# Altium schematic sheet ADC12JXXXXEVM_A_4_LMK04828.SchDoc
size 431 x 279 mm; Date: Not shown in title block; ApprovedBy: Not shown in title block; CheckedBy: Not shown in title block; Author: Not shown in title block; CompanyName: Not shown in title block; Engineer: Not shown in title block; Organization: Not shown in title block; Address1: Not shown in title block; Address2: Not shown in title block; Address3: Not shown in title block; Address4: Not shown in title block; DocumentNumber: 4; Revision: Use project parameter SCH_Rev; SheetNumber: 4; SheetTotal: 7; PageSetup: Record=PageOptions|CenterHorizontal=True|CenterVertical=True|PrintScale=0.47|XCorrection=1.00|YCorrection=1.00|PrintKind=0|BorderSize=5000000|LeftOffset=0|BottomOffset=0|Orientation=2|PaperLength=1000|PaperWidth=1000|Scale=100|PaperSource=7|PrintQuality=600|MediaType=1|DitherType=10|PaperKind=11" x 17"|PrintScaleMode=1
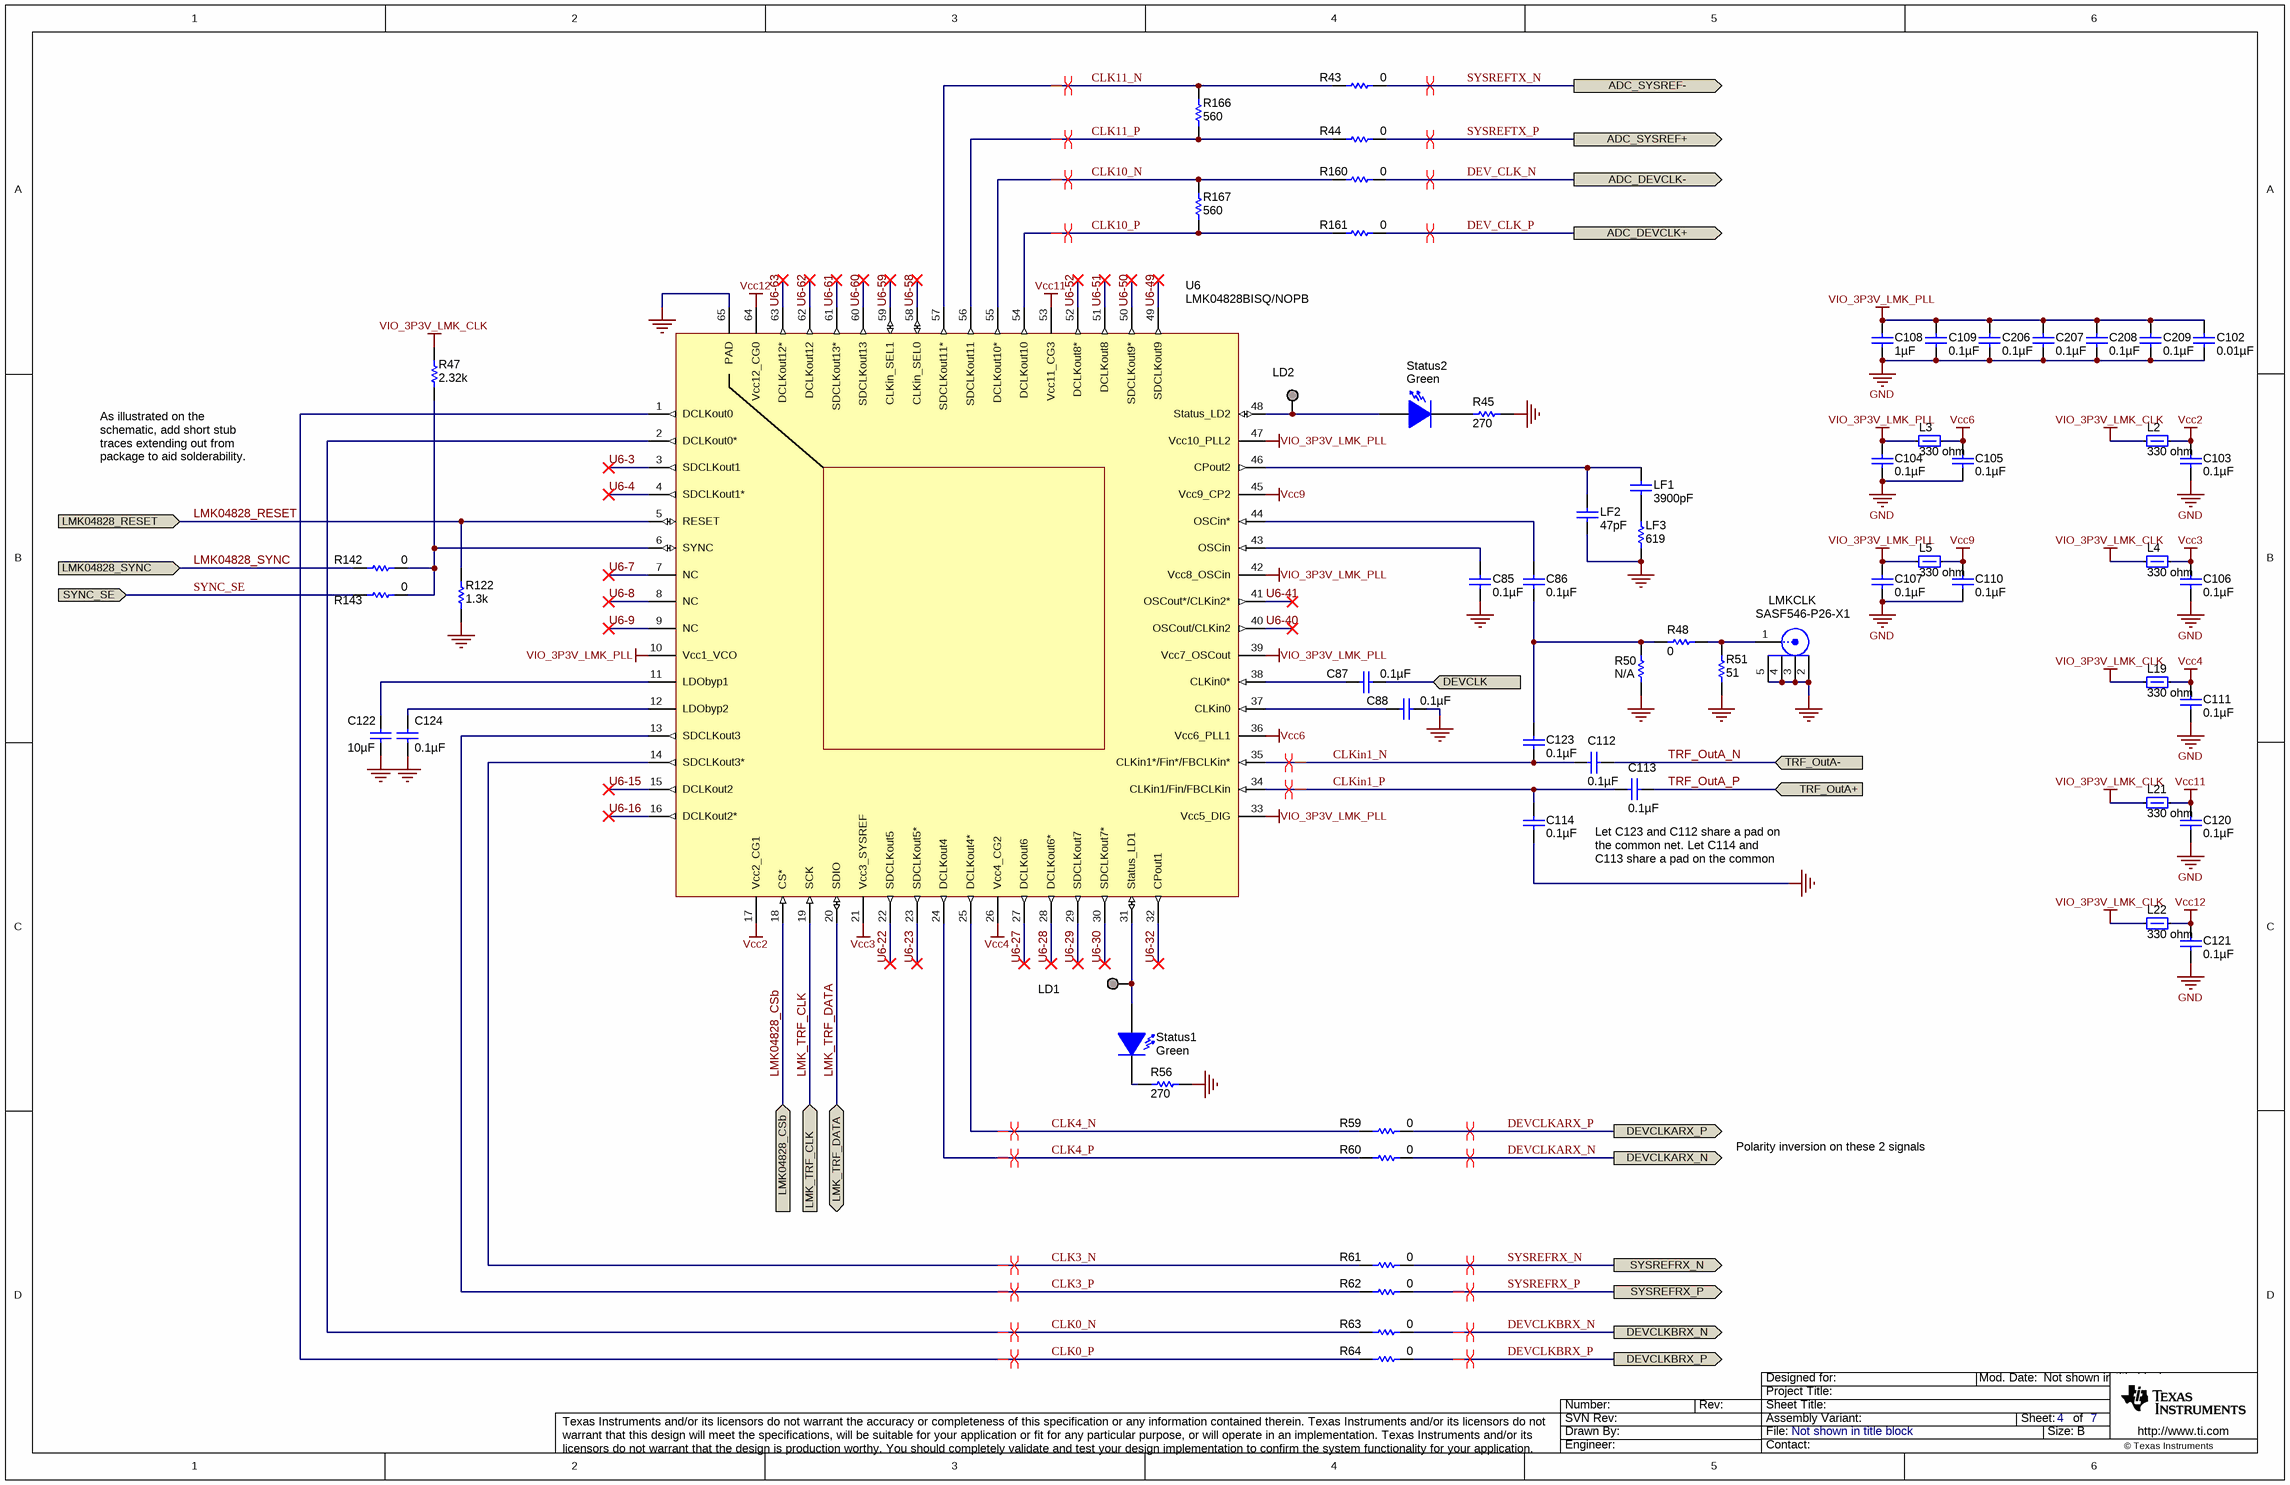
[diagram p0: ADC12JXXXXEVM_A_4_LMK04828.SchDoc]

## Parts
C85  ValueDisplayed: 0.1µF  [0402L]  (hidden comment: C1005X5R1A104K)
C86  ValueDisplayed: 0.1µF  [0402L]  (hidden comment: C1005X5R1A104K)
C87  ValueDisplayed: 0.1µF  [0402L]  (hidden comment: C1005X5R1A104K)
C88  ValueDisplayed: 0.1µF  [0402L]  (hidden comment: C1005X5R1A104K)
C102  ValueDisplayed: 0.01µF  [0402L]  (hidden comment: C1005X7R1C103K)
C103  ValueDisplayed: 0.1µF  [0402L]  (hidden comment: C1005X5R1A104K)
C104  ValueDisplayed: 0.1µF  [0402L]  (hidden comment: C1005X5R1A104K)
C105  ValueDisplayed: 0.1µF  [0402L]  (hidden comment: C1005X5R1A104K)
C106  ValueDisplayed: 0.1µF  [0402L]  (hidden comment: C1005X5R1A104K)
C107  ValueDisplayed: 0.1µF  [0402L]  (hidden comment: C1005X5R1A104K)
C108  ValueDisplayed: 1µF  [0603L]  (hidden comment: C1608X5R1C105K)
C109  ValueDisplayed: 0.1µF  [0402L]  (hidden comment: C1005X5R1A104K)
C110  ValueDisplayed: 0.1µF  [0402L]  (hidden comment: C1005X5R1A104K)
C111  ValueDisplayed: 0.1µF  [0402L]  (hidden comment: C1005X5R1A104K)
C112  ValueDisplayed: 0.1µF  [0402L]  (hidden comment: C1005X5R1A104K)
C113  ValueDisplayed: 0.1µF  [0402L]  (hidden comment: C1005X5R1A104K)
C114  ValueDisplayed: 0.1µF  [0402L]  (hidden comment: C1005X5R1A104K)
C120  ValueDisplayed: 0.1µF  [0402L]  (hidden comment: C1005X5R1A104K)
C121  ValueDisplayed: 0.1µF  [0402L]  (hidden comment: C1005X5R1A104K)
C122  ValueDisplayed: 10µF  [0805L]  (hidden comment: C0805C106K8PACTU)
C123  ValueDisplayed: 0.1µF  [0402L]  (hidden comment: C1005X5R1A104K)
C124  ValueDisplayed: 0.1µF  [0402L]  (hidden comment: C1005X5R1A104K)
C206  ValueDisplayed: 0.1µF  [0402L]  (hidden comment: C1005X5R1A104K)
C207  ValueDisplayed: 0.1µF  [0402L]  (hidden comment: C1005X5R1A104K)
C208  ValueDisplayed: 0.1µF  [0402L]  (hidden comment: C1005X5R1A104K)
C209  ValueDisplayed: 0.1µF  [0402L]  (hidden comment: C1005X5R1A104K)
L2  value 330 ohm  [0603]  (hidden comment: BLM18SG331TN1D)
L3  value 330 ohm  [0603]  (hidden comment: BLM18SG331TN1D)
L4  value 330 ohm  [0603]  (hidden comment: BLM18SG331TN1D)
L5  value 330 ohm  [0603]  (hidden comment: BLM18SG331TN1D)
L19  value 330 ohm  [0603]  (hidden comment: BLM18SG331TN1D)
L21  value 330 ohm  [0603]  (hidden comment: BLM18SG331TN1D)
L22  value 330 ohm  [0603]  (hidden comment: BLM18SG331TN1D)
LD1  TESTPOINT  [TESTPOINT]  (value not drawn)  (no BOM)
LD2  TESTPOINT  [TESTPOINT]  (value not drawn)  (no BOM)
LF1  ValueDisplayed: 3900pF  [0603L]  (hidden comment: C1608C0G1E392J)
LF2  ValueDisplayed: 47pF  [0603L]  (hidden comment: 06035A470JAT2A)
LF3  value 619  [0603L]  (hidden comment: RC0603FR-07619RL)
LMKCLK  SASF546-P26-X1  [CONN_LTI_SASF546-P26-X1]
R43  value 0  [0402L]  (hidden comment: CRCW04020000Z0ED)
R44  value 0  [0402L]  (hidden comment: CRCW04020000Z0ED)
R45  value 270  [0603L]  (hidden comment: CRCW0603270RJNEA)
R47  value 2.32k  [0603L]  (hidden comment: RC0603FR-072K32L)
R48  value 0  [0402L]  (hidden comment: CRCW04020000Z0ED)
R50  Used in BOM report  [0402L]  (value not drawn)
R51  value 51  [0402L]  (hidden comment: CRCW040251R0JNED)
R56  value 270  [0603L]  (hidden comment: CRCW0603270RJNEA)
R59  value 0  [0402L]  (hidden comment: CRCW04020000Z0ED)
R60  value 0  [0402L]  (hidden comment: CRCW04020000Z0ED)
R61  value 0  [0402L]  (hidden comment: CRCW04020000Z0ED)
R62  value 0  [0402L]  (hidden comment: CRCW04020000Z0ED)
R63  value 0  [0402L]  (hidden comment: CRCW04020000Z0ED)
R64  value 0  [0402L]  (hidden comment: CRCW04020000Z0ED)
R122  value 1.3k  [0603L]  (hidden comment: RC0603JR-071K3L)
R142  value 0  [0603L]  (hidden comment: ERJ-3GEY0R00V)
R143  value 0  [0603L]  (hidden comment: ERJ-3GEY0R00V)
R160  value 0  [0402L]  (hidden comment: CRCW04020000Z0ED)
R161  value 0  [0402L]  (hidden comment: CRCW04020000Z0ED)
R166  ValueDisplayed: 560  [0402L]  (hidden comment: CRCW0402560RJNED)
R167  ValueDisplayed: 560  [0402L]  (hidden comment: CRCW0402560RJNED)
Status1  value Green  [LED_LTST-C190]  (hidden comment: LTST-C190GKT)
Status2  value Green  [LED_LTST-C190]  (hidden comment: LTST-C190GKT)
U6  LMK04828BISQ/NOPB  [NKD0064A]

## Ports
ADC_DEVCLK+ (out), ADC_DEVCLK- (out), ADC_SYSREF+ (out), ADC_SYSREF- (out), DEVCLK (in), DEVCLKARX_N (out), DEVCLKARX_P (out), DEVCLKBRX_N (out), DEVCLKBRX_P (out), LMK04828_CSb (in), LMK04828_RESET (in), LMK04828_SYNC (in), LMK_TRF_CLK (in), LMK_TRF_DATA (bidir), SYNC_SE (in), SYSREFRX_N (out), SYSREFRX_P (out), TRF_OutA+ (in), TRF_OutA- (in)

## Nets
GND: C85.1 C88.2 C102.2 C103.2 C104.2 C105.2 C106.2 C107.2 C108.2 C109.2 C110.2 C111.2 C114.1 C120.2 C121.2 C122.2 C124.2 C206.2 C207.2 C208.2 C209.2 LF2.2 LF3.1 LMKCLK.2 LMKCLK.3 LMKCLK.4 LMKCLK.5 R45.1 R50.2 R51.1 R56.1 R122.1 U6.65(PAD)
Vcc2: C103.1 L2.2 U6.17(Vcc2_CG1)
Vcc3: C106.1 L4.2 U6.21(Vcc3_SYSREF)
Vcc4: C111.1 L19.2 U6.26(Vcc4_CG2)
Vcc6: C105.1 L3.2 U6.36(Vcc6_PLL1)
Vcc9: C110.1 L5.2 U6.45(Vcc9_CP2)
Vcc11: C120.1 L21.2 U6.53(Vcc11_CG3)
Vcc12: C121.1 L22.2 U6.64(Vcc12_CG0)
VIO_3P3V_LMK_CLK: L2.1 L4.1 L19.1 L21.1 L22.1 R47.2
VIO_3P3V_LMK_PLL: C102.1 C104.1 C107.1 C108.1 C109.1 C206.1 C207.1 C208.1 C209.1 L3.1 L5.1 U6.10(Vcc1_VCO) U6.33(Vcc5_DIG) U6.39(Vcc7_OSCout) U6.42(Vcc8_OSCin) U6.47(Vcc10_PLL2)
CLK0_N: R63.1 U6.2(DCLKout0*)
CLK0_P: R64.1 U6.1(DCLKout0)
CLK3_N: R61.1 U6.14(SDCLKout3*)
CLK3_P: R62.1 U6.13(SDCLKout3)
CLK4_N: R59.1 U6.25(DCLKout4*)
CLK4_P: R60.1 U6.24(DCLKout4)
CLK10_N: R160.1 R167.2 U6.55(DCLKout10*)
CLK10_P: R161.1 R167.1 U6.54(DCLKout10)
CLK11_N: R43.1 R166.2 U6.57(SDCLKout11*)
CLK11_P: R44.1 R166.1 U6.56(SDCLKout11)
CLKin1_N: C112.1 C123.1 U6.35(CLKin1*/Fin*/FBCLKin*)
CLKin1_P: C113.1 C114.2 U6.34(CLKin1/Fin/FBCLKin)
DEV_CLK_N: R160.2 ; port ADC_DEVCLK-
DEV_CLK_P: R161.2 ; port ADC_DEVCLK+
DEVCLK: C87.2 ; port DEVCLK
DEVCLKARX_N: R60.2 ; port DEVCLKARX_N
DEVCLKARX_P: R59.2 ; port DEVCLKARX_P
DEVCLKBRX_N: R63.2 ; port DEVCLKBRX_N
DEVCLKBRX_P: R64.2 ; port DEVCLKBRX_P
LMK04828_CSb: U6.18(CS*) ; port LMK04828_CSb
LMK04828_RESET: R122.2 U6.5(RESET) ; port LMK04828_RESET
LMK04828_SYNC: R142.1 ; port LMK04828_SYNC
LMK_TRF_CLK: U6.19(SCK) ; port LMK_TRF_CLK
LMK_TRF_DATA: U6.20(SDIO) ; port LMK_TRF_DATA
SYNC_SE: R143.1 ; port SYNC_SE
SYSREFRX_N: R61.2 ; port SYSREFRX_N
SYSREFRX_P: R62.2 ; port SYSREFRX_P
SYSREFTX_N: R43.2 ; port ADC_SYSREF-
SYSREFTX_P: R44.2 ; port ADC_SYSREF+
TRF_OutA_N: C112.2 ; port TRF_OutA-
TRF_OutA_P: C113.2 ; port TRF_OutA+
U6-3: U6.3(SDCLKout1)
U6-4: U6.4(SDCLKout1*)
U6-7: U6.7(NC)
U6-8: U6.8(NC)
U6-9: U6.9(NC)
U6-15: U6.15(DCLKout2)
U6-16: U6.16(DCLKout2*)
U6-22: U6.22(SDCLKout5)
U6-23: U6.23(SDCLKout5*)
U6-27: U6.27(DCLKout6)
U6-28: U6.28(DCLKout6*)
U6-29: U6.29(SDCLKout7)
U6-30: U6.30(SDCLKout7*)
U6-32: U6.32(CPout1)
U6-40: U6.40(OSCout/CLKin2)
U6-41: U6.41(OSCout*/CLKin2*)
U6-49: U6.49(SDCLKout9)
U6-50: U6.50(SDCLKout9*)
U6-51: U6.51(DCLKout8)
U6-52: U6.52(DCLKout8*)
U6-58: U6.58(CLKin_SEL0)
U6-59: U6.59(CLKin_SEL1)
U6-60: U6.60(SDCLKout13)
U6-61: U6.61(SDCLKout13*)
U6-62: U6.62(DCLKout12)
U6-63: U6.63(DCLKout12*)
NetC85_2: C85.2 U6.43(OSCin)
NetC86_1: C86.1 C123.2 R48.1 R50.1
NetC86_2: C86.2 U6.44(OSCin*)
NetC87_1: C87.1 U6.38(CLKin0*)
NetC88_1: C88.1 U6.37(CLKin0)
NetC122_1: C122.1 U6.11(LDObyp1)
NetC124_1: C124.1 U6.12(LDObyp2)
NetLD1_1: LD1.1 Status1.1(A) U6.31(Status_LD1)
NetLD2_1: LD2.1 Status2.1(A) U6.48(Status_LD2)
NetLF1_1: LF1.1 LF2.1 U6.46(CPout2)
NetLF1_2: LF1.2 LF3.2
NetLMKCLK_1: LMKCLK.1 R48.2 R51.2
NetR45_2: R45.2 Status2.2(K)
NetR47_1: R47.1 R142.2 R143.2 U6.6(SYNC)
NetR56_2: R56.2 Status1.2(K)

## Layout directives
differential pair: CLK0_N, CLK0_P, CLK3_N, CLK3_P, CLK4_N, CLK4_P, CLK10_N, CLK10_P, CLK11_N, CLK11_P, CLKin1_N, CLKin1_P, DEV_CLK_N, DEV_CLK_P, DEVCLKARX_N, DEVCLKARX_P, DEVCLKBRX_N, DEVCLKBRX_P, SYSREFRX_N, SYSREFRX_P, SYSREFTX_N, SYSREFTX_P

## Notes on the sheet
- As illustrated on the schematic, add short stub traces extending out from package to aid solderability.
- (near C113) Let C123 and C112 share a pad on the common net. Let C114 and C113 share a pad on the common net.
- Polarity inversion on these 2 signals

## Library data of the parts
C85-C88 C103-C107 C109-C114 C120 C121 C123 C124 C206-C209 = C1005X5R1A104K: CAP, CERM, 0.1uF, 10V, +/-10%, X5R, 0402; Manufacturer: TDK; Polarized: N; CompType: Capacitor; U/M: EA; Cap_F: 0.0000001; Tolerance_%: 10; ESR_Ohm: 0.0186; Value1: 0.0186 ohm; TaMin_C: -55; TaMax_C: 85; Cap_Case: 0402
C102 = C1005X7R1C103K: CAP, CERM, 0.01uF, 16V, +/-10%, X7R, 0402; Manufacturer: TDK; Polarized: N; CompType: Capacitor; U/M: EA; Cap_F: 0.00000001; Tolerance_%: 10; ESR_Ohm: 0.0623; Value1: 0.0623 ohm; VDC_V: 16; TaMin_C: -55; TaMax_C: 125; Cap_Case: 0402
C108 = C1608X5R1C105K: CAP, CERM, 1uF, 16V, +/-10%, X5R, 0603; Manufacturer: TDK; Polarized: N; CompType: Capacitor; U/M: EA; Cap_F: 0.000001; Tolerance_%: 10; ESR_Ohm: 0.0057; Value1: 0.0057 ohm; VDC_V: 16; TaMin_C: -55; TaMax_C: 85; Cap_Case: 0603
C122 = C0805C106K8PACTU: CAP, CERM, 10uF, 10V, +/-10%, X5R, 0805; Manufacturer: Kemet; Cap_Case: 0805; ESR_Ohm: 0.003; IRMS_A: 11.43; Polarized: N; TaMax_C: 85; TaMin_C: -55; Tolerance_%: 10; Cap_F: 10.0E-6; CompType: Capacitor; Value1: 0.003 ohm
L2-L5 L19 L21 L22 = BLM18SG331TN1D: 1.5A Ferrite Bead, 330 ohm @ 100MHz, SMD; Manufacturer: MuRata; Imax_A: 1.5; DCR_ohm: 0.07; Value1: 0.07 ohm; ZTyp@100MHz_Ohm: 330; U/M: EA
LD1 LD2 = TESTPOINT: TEST POINT.  No entry in BOM.
LF1 = C1608C0G1E392J: CAP, CERM, 3900pF, 25V, +/-5%, C0G/NP0, 0603; Manufacturer: TDK; Polarized: N; CompType: Capacitor; U/M: EA; Cap_F: 0.0000000039; Tolerance_%: 5; VDC_V: 25; TaMin_C: -55; TaMax_C: 125; Cap_Case: 0603
LF2 = 06035A470JAT2A: CAP, CERM, 47pF, 50V, +/-5%, C0G/NP0, 0603; Manufacturer: AVX; Polarized: N; CompType: Capacitor; U/M: EA; Cap_F: 0.000000000047; Tolerance_%: 5; ESR_Ohm: 0.174; Value1: 0.174 ohm; VDC_V: 50; TaMin_C: -55; TaMax_C: 125; Cap_Case: 0603
LF3 = RC0603FR-07619RL: RES, 619 ohm, 1%, 0.1W, 0603; Manufacturer: Yageo America; Alternate Manufacturer: Any; Alternate PartNumber: Equivalent; CompType: Resistor; Value_Code: 619R; Tolerance_%: 1; Power_W: 0.1; VDC_V: 150; TempCo: 200 ppm/C; EIA_Code: E96; U/M: EA
LMKCLK = SASF546-P26-X1: Connector, SMA,Vertical, Thru hole w/SMT center pin; Manufacturer: Lighthorse Technologies; U/M: EA
R43 R44 R59-R64 R160 R161 = CRCW04020000Z0ED: RES, 0 ohm, 5%, 0.063W, 0402; Manufacturer: Vishay-Dale; CompType: Resistor; Value_Code: 0000; Tolerance_%: 5; Power_W: 0.063; VDC_V: 50; TempCo: 200 ppm/C; EIA_Code: E24; U/M: EA
R45 R56 = CRCW0603270RJNEA: RES, 270 ohm, 5%, 0.1W, 0603; Manufacturer: Vishay-Dale; Alternate Manufacturer: Any; Alternate PartNumber: Equivalent; CompType: Resistor; Value_Code: 270R; Tolerance_%: 5; Power_W: 0.1; VDC_V: 75; TempCo: 200 ppm/C; EIA_Code: E24; U/M: EA
R47 = RC0603FR-072K32L: RES, 2.32k ohm, 1%, 0.1W, 0603; Manufacturer: Yageo America; CompType: Resistor; Res_ohm: 2320; Value_Code: 2k32; Tolerance_%: 1; Power_W: 0.1; VDC_V: 150; TempCo: 200 ppm/C; EIA_Code: E96; U/M: EA
R48 = CRCW04020000Z0ED: RES, 0 ohm, 5%, 0.063W, 0402; Manufacturer: Vishay-Dale; Alternate Manufacturer: Any; Alternate PartNumber: Equivalent; CompType: Resistor; Value_Code: 0000; Tolerance_%: 5; Power_W: 0.063; VDC_V: 50; TempCo: 200 ppm/C; EIA_Code: E24; U/M: EA
R50 = Resistor: RES, xxx ohm, x%, xW, [PackageReference]; U/M: EA
R51 = CRCW040251R0JNED: RES, 51 ohm, 5%, 0.063W, 0402; Manufacturer: Vishay-Dale; Alternate Manufacturer: Any; Alternate PartNumber: Equivalent; CompType: Resistor; Value_Code: 51R0; Tolerance_%: 5; Power_W: 0.063; VDC_V: 50; TempCo: 200 ppm/C; EIA_Code: E24; U/M: EA
R122 = RC0603JR-071K3L: RES, 1.3k ohm, 5%, 0.1W, 0603; Manufacturer: Yageo America; CompType: Resistor; Res_ohm: 1300; Value_Code: 1k30; Tolerance_%: 5; Power_W: 0.1; VDC_V: 50; TempCo: 100 ppm/C; EIA_Code: E24; U/M: EA
R142 R143 = ERJ-3GEY0R00V: RES, 0 ohm, 5%, 0.1W, 0603; Manufacturer: Panasonic; CompType: Resistor; Value_Code: 0000; Tolerance_%: 5; Power_W: 0.1; VDC_V: 50; TempCo: 600 ppm/C; EIA_Code: E24; U/M: EA
R166 R167 = CRCW0402560RJNED: RES, 560, 5%, 0.063 W, 0402; Manufacturer: Vishay-Dale; CompType: Resistor; Value: 560; Value_Code: 560R; Tolerance_%: 5; Power_W: 0.063; Value2: 0.063W; VDC_V: 50; TempCo: 200 ppm/C; EIA_Code: E24; U/M: EA
Status1 Status2 = LTST-C190GKT: LED, Green, SMD; Manufacturer: Lite-On; Vf_V: 2.1; Value2: 2.1V; Io_A: 0.02; Power_TotalModule: 0.1; Value1: 0.1W; U/M: EA
U6 = LMK04828BISQ/NOPB: Low-Noise Clock Jitter Cleaner with Dual Loop PLLs, NKD0064A; Alternate Manufacturer: None; Manufacturer: Texas Instruments; SymbolCreator: a0411947/a0412235; CompType: IC; U/M: EA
